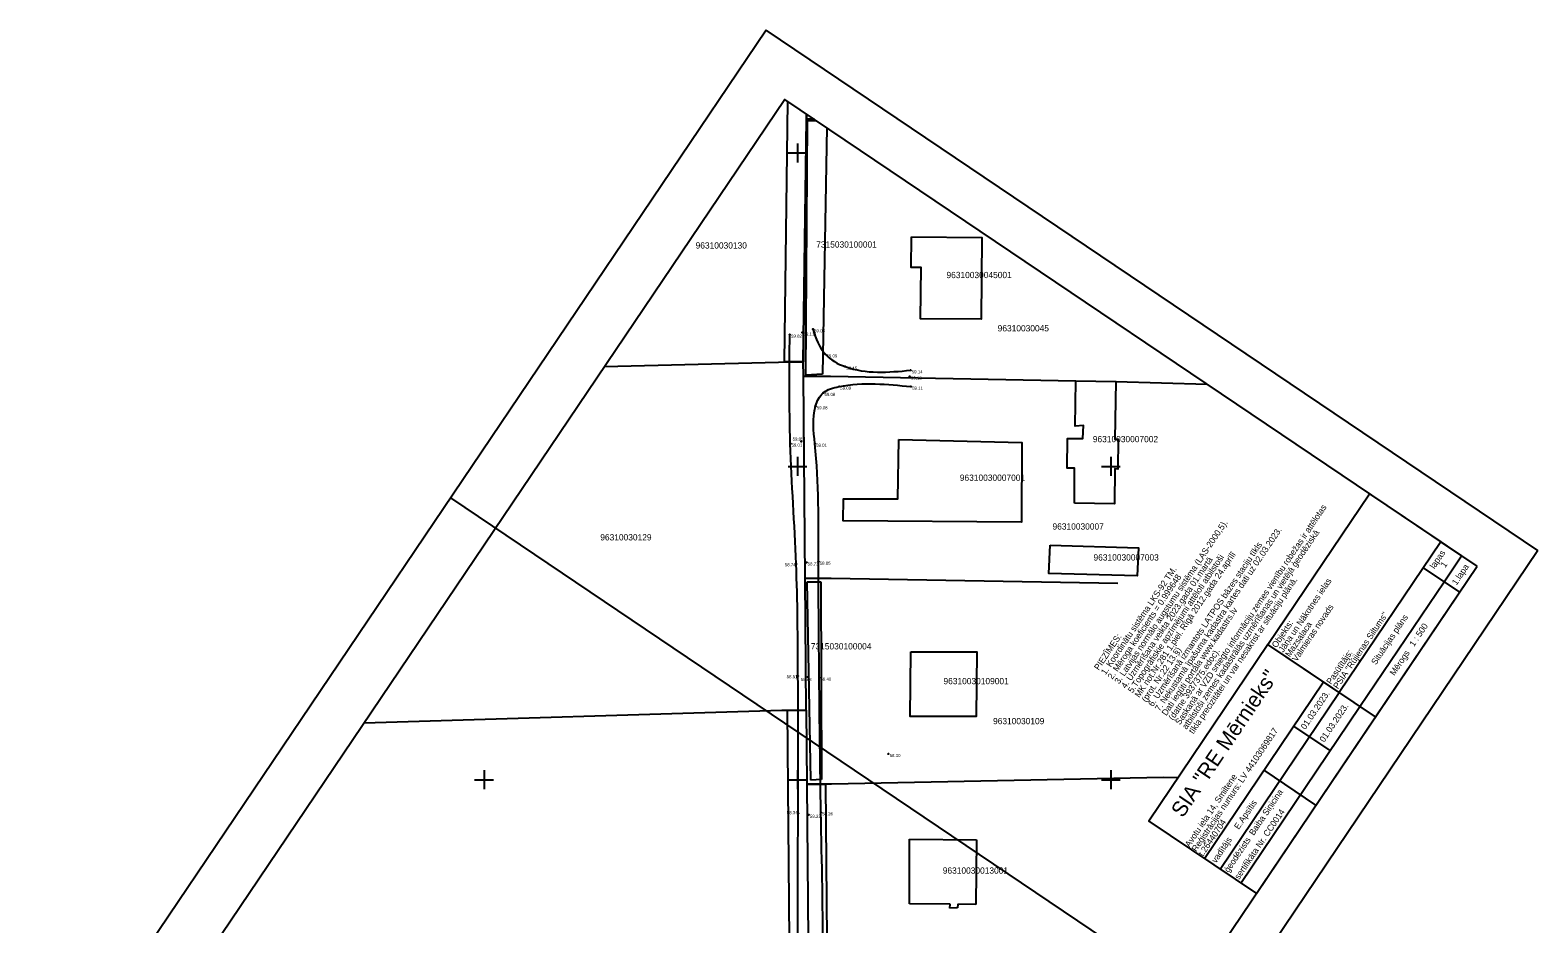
# Model space of a CAD drawing. Extents: x 562228 to 562468, y 414712 to 414970.
# Drawn here: x 562227.6 to 562468.1, y 414827 to 414969.6 of the extents above; entities that cross this region are included whole.
import ezdxf

# ---------------------------------------------------------------- set-up
doc = ezdxf.new("R2010")
doc.units = 0
for name, color, linetype in [('7315030100', 7, 'Continuous'), ('7315030100_TEXT', 7, 'Continuous'), ('BUVE_EKAS_UZMR_####_#', 7, 'Continuous'), ('BUVE_EKAS_UZMR_TKST_#', 7, 'Continuous'), ('BUVE_EKAS_VEKT_####_#', 7, 'Continuous'), ('BUVE_EKAS_VEKT_TKST_#', 7, 'Continuous'), ('CELI_CMAL_####_####_#', 7, 'Continuous'), ('GEOD_ELEM_####_####_#', 7, 'Continuous'), ('RAMI_PLAN_####_TKST_#', 7, 'Continuous'), ('RELJ_AATZ_####_TKST_#', 7, 'Continuous'), ('RELJ_ELEM_####_####_#', 7, 'Continuous'), ('ROBZ_UZMR_####_####_#', 7, 'Continuous'), ('ROBZ_UZMR_####_TKST_#', 7, 'Continuous')]:
    doc.layers.add(name, color=color, linetype=linetype)

msp = doc.modelspace()

# ---------------------------------------------------------------- linework, layer by layer
at = {"layer": '7315030100'}
for p, q in [((562347.92, 414916.66), (562348.49, 414958.21)), ((562351.45, 414955.42), (562350.93, 414916.66)), ((562351.32, 414914.54), (562351.62, 414955.19)), ((562351.46, 414956.21), (562351.45, 414955.42)), ((562351.62, 414955.19), (562353.03, 414955.15)), ((562354.67, 414954.05), (562354.01, 414914.69)), ((562350.93, 414916.66), (562347.92, 414916.66)), ((562354.01, 414914.69), (562351.32, 414914.54)), ((562351.53, 414881.57), (562353.71, 414881.57)), ((562352.13, 414849.92), (562351.53, 414881.57)), ((562353.71, 414881.57), (562353.84, 414850.04)), ((562348.4, 414861.02), (562351.4, 414861.11)), ((562348.71, 414824.34), (562348.4, 414861.02)), ((562351.4, 414861.11), (562351.5, 414849.28)), ((562351.5, 414849.28), (562351.71, 414824.43)), ((562351.5, 414849.28), (562354.48, 414849.26)), ((562353.84, 414850.04), (562352.13, 414849.92)), ((562354.48, 414849.26), (562354.71, 414824.51))]:
    msp.add_line(p, q, dxfattribs=at)
at = {"layer": 'BUVE_EKAS_UZMR_####_#'}
for points in [[(562368.18, 414936.6), (562379.43, 414936.49), (562379.3, 414923.46), (562369.66, 414923.55), (562369.74, 414931.71), (562368.13, 414931.72)], [(562394.19, 414894.15), (562394.22, 414899.7), (562393.06, 414899.72), (562393.08, 414904.46), (562395.53, 414904.42), (562395.66, 414906.51), (562394.31, 414906.43), (562394.41, 414913.63), (562400.78, 414913.55), (562400.65, 414904.35), (562401.19, 414904.34), (562401.1, 414899.57), (562400.63, 414899.58), (562400.6, 414894.03)], [(562366.18, 414904.29), (562385.8, 414903.78), (562385.74, 414891.09), (562357.32, 414891.33), (562357.35, 414894.83), (562366, 414894.81)], [(562390.31, 414887.44), (562404.4, 414887.02), (562404.18, 414882.51), (562390.09, 414882.93)], [(562368.07, 414870.38), (562378.62, 414870.39), (562378.53, 414860.1), (562367.97, 414860.09)]]:
    msp.add_lwpolyline(points, close=True, dxfattribs=at)
at = {"layer": 'BUVE_EKAS_VEKT_####_#'}
for p, q in [((562367.88, 414830.19), (562367.89, 414840.52)), ((562367.89, 414840.52), (562378.55, 414840.41)), ((562378.55, 414840.41), (562378.44, 414830.1)), ((562374.35, 414830.13), (562367.88, 414830.19)), ((562374.34, 414829.5), (562374.35, 414830.13)), ((562375.57, 414830.12), (562375.56, 414829.54)), ((562378.44, 414830.1), (562375.57, 414830.12)), ((562375.56, 414829.54), (562374.34, 414829.5))]:
    msp.add_line(p, q, dxfattribs=at)
at = {"layer": 'CELI_CMAL_####_####_#'}
for points in [[(562352.47, 414921.89), (562354.45, 414917.88), (562357.62, 414915.91), (562368.05, 414915.33)], [(562351.74, 414800.51), (562351.33, 414803.68), (562350.16, 414820.75), (562350.12, 414844.64), (562350.09, 414866.54), (562349.8, 414884.43), (562348.86, 414903.65), (562348.78, 414921.02)], [(562354.72, 414801.85), (562353.99, 414814.52), (562354.03, 414820.78), (562353.75, 414844.81), (562353.48, 414866.3), (562353.37, 414884.8), (562352.79, 414903.63), (562352.89, 414909.6), (562354.13, 414911.73), (562356.64, 414912.73), (562368.11, 414912.72)]]:
    msp.add_spline(points, degree=3, dxfattribs=at)
at = {"layer": 'GEOD_ELEM_####_####_#'}
for p, q in [((562350, 414951.5), (562350, 414950)), ((562348.5, 414950), (562350, 414950)), ((562350, 414950), (562350, 414948.5)), ((562350, 414950), (562351.5, 414950)), ((562348.5, 414900), (562350, 414900)), ((562350, 414901.5), (562350, 414900)), ((562350, 414900), (562350, 414898.5)), ((562350, 414900), (562351.5, 414900)), ((562398.5, 414900), (562400, 414900)), ((562400, 414901.5), (562400, 414900)), ((562400, 414900), (562400, 414898.5)), ((562400, 414900), (562401.5, 414900)), ((562298.5, 414850), (562300, 414850)), ((562300, 414851.5), (562300, 414850)), ((562300, 414850), (562300, 414848.5)), ((562300, 414850), (562301.5, 414850)), ((562348.5, 414850), (562350, 414850)), ((562350, 414851.5), (562350, 414850)), ((562350, 414850), (562350, 414848.5)), ((562350, 414850), (562351.5, 414850)), ((562398.5, 414850), (562400, 414850)), ((562400, 414851.5), (562400, 414850)), ((562400, 414850), (562400, 414848.5)), ((562400, 414850), (562401.5, 414850))]:
    msp.add_line(p, q, dxfattribs=at)
at = {"layer": 'RAMI_PLAN_####_TKST_#'}
for p, q in [((562345.01, 414969.6), (562227.59, 414795.49)), ((562468.13, 414886.57), (562345.01, 414969.6)), ((562417.81, 414811.95), (562294.69, 414894.98)), ((562458.44, 414884.06), (562452.64, 414887.98)), ((562468.13, 414886.57), (562350.71, 414712.46)), ((562453.16, 414881.59), (562455.96, 414885.74)), ((562442.23, 414860.02), (562458.44, 414884.06)), ((562449.85, 414883.83), (562455.65, 414879.92)), ((562439.74, 414861.7), (562453.16, 414881.59)), ((562414.93, 414837.42), (562433.94, 414865.61)), ((562417.42, 414835.74), (562436.43, 414863.93)), ((562420.73, 414833.51), (562439.74, 414861.7)), ((562434.99, 414854.65), (562429.19, 414858.56)), ((562432.73, 414845.92), (562424.44, 414851.51))]:
    msp.add_line(p, q, dxfattribs=at)
msp.add_lwpolyline([(562458.44, 414884.06), (562347.98, 414958.55), (562243.14, 414803.09), (562353.61, 414728.6)], close=True, dxfattribs=at)
for points in [[(562425.05, 414871.6), (562441.27, 414895.64), (562452.64, 414887.98), (562436.43, 414863.93), (562425.05, 414871.6)], [(562442.23, 414860.02), (562425.05, 414871.6), (562406.04, 414843.41), (562423.22, 414831.83), (562442.23, 414860.02)]]:
    msp.add_lwpolyline(points, dxfattribs=at)
at = {"layer": 'RELJ_ELEM_####_####_#'}
for centre in [(562350.79, 414921.36), (562352.47, 414921.89), (562348.78, 414921.02), (562354.45, 414917.88), (562357.62, 414915.91), (562367.92, 414914.34), (562368.05, 414915.33), (562354.13, 414911.73), (562356.64, 414912.73), (562368.11, 414912.72), (562352.89, 414909.6), (562348.86, 414903.65), (562350.64, 414903.97), (562352.79, 414903.63), (562349.8, 414884.43), (562351.44, 414884.68), (562353.37, 414884.8), (562350.09, 414866.54), (562351.65, 414866.39), (562353.48, 414866.3), (562364.52, 414854.11), (562350.12, 414844.64), (562351.8, 414844.42), (562353.75, 414844.81)]:
    msp.add_circle(centre, 0.05, dxfattribs=at)
at = {"layer": 'ROBZ_UZMR_####_####_#'}
for p, q in [((562350.93, 414916.66), (562351.45, 414955.42)), ((562351.45, 414955.42), (562351.46, 414956.21)), ((562352.66, 414955.4), (562351.45, 414955.42)), ((562319.23, 414915.92), (562346.97, 414916.63)), ((562346.97, 414916.63), (562350.93, 414916.66)), ((562350.95, 414914.37), (562350.93, 414916.66)), ((562350.95, 414914.37), (562355.26, 414914.41)), ((562351.22, 414882.09), (562350.95, 414914.37)), ((562355.26, 414914.41), (562394.41, 414913.63)), ((562394.41, 414913.63), (562400.78, 414913.55)), ((562400.78, 414913.55), (562415.38, 414913.1)), ((562355.38, 414882.12), (562351.22, 414882.09)), ((562351.4, 414861.11), (562351.22, 414882.09)), ((562401.14, 414881.32), (562355.38, 414882.12)), ((562280.89, 414859.07), (562347.53, 414861.08)), ((562347.53, 414861.08), (562351.4, 414861.11)), ((562351.4, 414861.11), (562351.5, 414849.28)), ((562355.45, 414849.31), (562351.5, 414849.28)), ((562351.5, 414849.28), (562351.71, 414824.43)), ((562408.41, 414850.33), (562355.45, 414849.31)), ((562410.69, 414850.29), (562408.41, 414850.33))]:
    msp.add_line(p, q, dxfattribs=at)

# ---------------------------------------------------------------- texts
at = {"layer": '7315030100_TEXT'}
for s, p in [('7315030100001', (562353, 414934.9)), ('7315030100004', (562352.14, 414870.79))]:
    msp.add_text(s, height=1, dxfattribs=at).set_placement(p)
at = {"layer": 'BUVE_EKAS_UZMR_TKST_#'}
for s, p in [('96310030045001', (562373.78, 414930.03)), ('96310030007002', (562397.13, 414903.85)), ('96310030007001', (562375.91, 414897.69)), ('96310030007003', (562397.24, 414884.97)), ('96310030109001', (562373.3, 414865.24))]:
    msp.add_text(s, height=1, dxfattribs=at).set_placement(p)
at = {"layer": 'BUVE_EKAS_VEKT_TKST_#'}
msp.add_text('96310030013001', height=1, dxfattribs=at).set_placement((562373.19, 414835.01))
at = {"layer": 'RAMI_PLAN_####_TKST_#'}
for s, height, rotation, p in [('Saskaņā ar VZD sniegto informāciju zemes vienību robežas ir attēlotas ', 1, 56.0365, (562411.02, 414858.66)), ('3. Latvijas normālo augstumu sistēma (LAS-2000,5).', 1, 56.0365, (562401.32, 414865.2)), ('6. Uzmērīšanā izmantots LATPOS bāzes staciju tīkls', 1, 56.0365, (562406.71, 414861.57)), ('7. Nekustamā īpašuma kadastra kartes dati uz 02.03.2023.', 1, 56.0365, (562407.78, 414860.84)), ('atbilstoši zemes kadastrālās uzmērīšanas un vietējā ģeodēziskā ', 1, 56.0365, (562412.1, 414857.94)), ('4. Uzmērīšana veikta 2023.gada 01.martā', 1, 56.0365, (562402.39, 414864.47)), ('5.Topogrāfiskie apzīmējumi attēloti atbilstoši', 1, 56.0365, (562403.47, 414863.75)), ('MK not.Nr.281 1.piel. Rīgā 2012.gada 24.aprīlī', 1, 56.0365, (562404.55, 414863.02)), ('lapas', 1, 56.0063, (562451.64, 414883.56)), ('1. Koordinātu sistēma LKS-92 TM.', 1, 56.0365, (562399.16, 414866.65)), ('   1', 1, 56.0063, (562452.72, 414882.83)), ('1.lapa', 1, 56.0063, (562455.15, 414880.96)), ('2. Mēroga koeficients = 0.999648', 1, 56.0365, (562400.24, 414865.93)), ('tīkla precizitātei un var nesakrist ar situāciju plānā.', 1, 56.0365, (562413.18, 414857.21)), ('Jāņa un Nākotnes ielas', 1, 56.005, (562427.5, 414870.22)), ('Dati iegūti portāla www.kadastrs.lv ', 1, 56.0365, (562408.86, 414860.12)), ('Valmieras novads', 1, 56.005, (562429.66, 414868.76)), ("PSIA ''Rūjienas Siltums''", 1, 56.005, (562436.22, 414864.4)), ('Situācijas plāns', 1, 56.006, (562442.28, 414868.23)), ('Objekts: ', 1, 56.005, (562426.42, 414870.95)), ('Mazsalaca', 1, 56.005, (562428.58, 414869.49)), ('Mērogs   1 : 500', 1, 56.0063, (562445.25, 414866.53)), ('PIEZĪMES:', 1, 56.0365, (562398.08, 414867.38)), ('(prot. Nr.22 13.§)', 1, 56.0365, (562405.63, 414862.29)), ('(datne 3937375.edoc).', 1, 56.0365, (562409.94, 414859.39)), ('Pasūtītājs:', 1, 56.005, (562435.14, 414865.13)), ('SIA "RE Mērnieks"', 2.4559, 56.0063, (562411.48, 414843.79)), ('01.03.2023.', 1, 56.0063, (562431.04, 414857.92)), ('01.03.2023.', 1, 56.0063, (562434.03, 414855.9)), ('Reģistrācijas numurs: LV 44103069817', 1, 56.0063, (562413.64, 414838.43)), ('Avotu iela 14, Smiltene', 1, 56.0063, (562412.56, 414839.16)), ('ģeodēzists  Baiba Siņicina', 1, 56.0063, (562418.81, 414835.11)), ('vadītājs     E.Apsītis', 1, 56.0063, (562416.8, 414836.62)), ('sertifikāta Nr. CC0014', 1, 56.0063, (562420.46, 414833.99)), ('t.26440704', 1, 56.0063, (562414.72, 414837.7))]:
    msp.add_text(s, height=height, rotation=rotation, dxfattribs=at).set_placement(p)
at = {"layer": 'RELJ_AATZ_####_TKST_#'}
for s, p in [(' 59.11', (562350.79, 414920.86)), (' 59.03', (562352.47, 414921.39)), (' 59.02', (562348.78, 414920.52)), (' 59.09', (562354.45, 414917.38)), (' 59.15', (562357.62, 414915.41)), (' 59.12', (562367.92, 414913.84)), (' 59.14', (562368.05, 414914.83)), (' 59.08', (562354.13, 414911.23)), (' 59.09', (562356.64, 414912.23)), (' 59.11', (562368.11, 414912.22)), (' 59.08', (562352.89, 414909.1)), (' 59.05', (562349.04, 414904.12)), (' 59.01', (562348.86, 414903.15)), (' 59.01', (562352.79, 414903.13)), (' 58.74', (562347.8, 414884.06)), (' 58.73', (562351.44, 414884.18)), (' 58.65', (562353.37, 414884.3)), (' 58.51', (562348.09, 414866.2)), (' 58.48', (562350.33, 414865.75)), (' 58.40', (562353.48, 414865.8)), (' 58.30', (562364.52, 414853.61)), (' 58.34', (562348.11, 414844.5)), (' 58.33', (562351.8, 414843.92)), (' 58.26', (562353.75, 414844.31))]:
    msp.add_text(s, height=0.5, dxfattribs=at).set_placement(p)
at = {"layer": 'ROBZ_UZMR_####_TKST_#'}
for s, p in [('96310030130', (562333.76, 414934.75)), ('96310030045', (562381.95, 414921.53)), ('96310030007', (562390.7, 414889.91)), ('96310030129', (562318.55, 414888.18)), ('96310030109', (562381.21, 414858.86))]:
    msp.add_text(s, height=1, dxfattribs=at).set_placement(p)

doc.saveas('drawing.dxf')
